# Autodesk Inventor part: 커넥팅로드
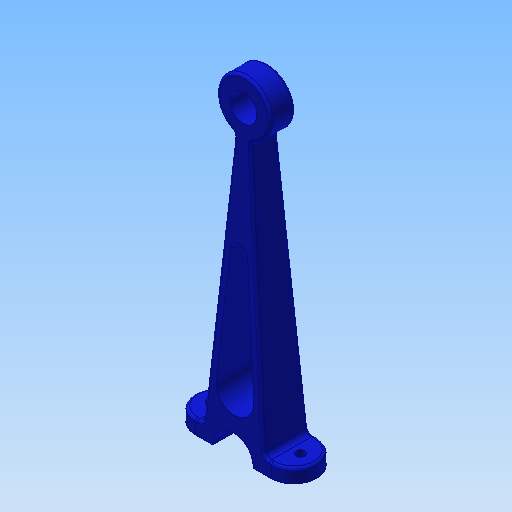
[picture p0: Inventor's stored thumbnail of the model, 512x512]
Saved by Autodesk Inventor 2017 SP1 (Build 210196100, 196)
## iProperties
Created: 2017-05
Part Number: 커넥팅로드
Material: 강철, 탄소
Document SubType Name: Modeling
Designer: mduedu
Density: 7.87 g/cm^3
Mass: 120.511 g
Surface Area: 85.3888 cm^2
Volume: 15.3127 cm^3
Appearance: 파란색 - 벽 페인트 - 무광
Author: mduedu
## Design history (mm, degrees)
sketch "스케치1"
  geometry: L1 (-22.5, 0)-(22.5, 0); L2 (22.5, 0)-(22.5, 5); L3 (-22.5, 5)-(-22.5, 0); L4 (-11.352, 5)-(-3, 100.461); L5 (0, 110)-(0, 0); L6 (11.352, 5)-(3, 100.461); L7 (22.5, 5)-(11.352, 5); L8 (-11.352, 5)-(-22.5, 5); C1 r 5 at (0, 110); A1 r 10 centre (0, 110) between (3, 100.461) and (-3, 100.461); 1 further point
  constraints: 16 end point, 4 parallel, 2 centre point, 2 coincident, 2 point on circle, 2 symmetric about line, 1 horizontal, 1 midpoint, 1 perpendicular, 1 vertical alignment
  dimensions: "d0" = 5 distance of L1.end L2.end; "d2" = 45 distance of L1.start L1.end; "d3" = 20 diameter of A1; "d4" = 10 diameter of C1; "d5" = 110 distance from line of L1 L5.start; "d6" = 5 deg angle of L5 L4; "d7" = 3 distance from line of L4.end L5
extrude "돌출1" new body sketch "스케치1" distance "d8" = 8.5; taper "d9" = 0 deg
sketch "스케치2"
  geometry: C1 r 7.5 at (0, 0); 1 further point
  constraints: 1 centre point, 1 coincident
  dimensions: "d10" = 15 diameter of C1
extrude "돌출2" cut sketch "스케치2" stored distance "d11" = 8.5; taper "d12" = 0 deg
sketch "스케치3"
  geometry: L1 (-3, 100.461)-(-11.352, 5) reference; L2 (11.352, 5)-(3, 100.461) reference; L3 (-3.154, 64.276)-(-6.975, 20.61); L4 (6.975, 20.61)-(3.154, 64.276); A1 r 3.166 centre (0, 64) between (3.154, 64.276) and (-3.154, 64.276); A2 r 7.001 centre (0, 20) between (-6.975, 20.61) and (6.975, 20.61); 1 further point
  constraints: 4 end point, 4 point on circle, 4 tangent, 2 centre point, 2 parallel, 1 vertical alignment
  dimensions: "d15" = 3 distance between parallel lines of L2 L4; "d16" = 44 distance of A2.centre A1.centre; "d17" = 20 distance of A2.centre point (0, 0)
extrude "돌출3" cut sketch "스케치3" stored distance "d18" = 8.5; taper "d19" = 0 deg
fillet "모깎기1" dims "d20" = 2
fillet "모깎기2" dims "d21" = 2
feature "면 기울기1" dims angle "d22" = 2 deg
fillet "모깎기3"
fillet "모깎기4"
fillet "모깎기5" dims "d28" = 1
sketch "스케치5"
  geometry: 3 further points
  constraints: 2 horizontal alignment
  dimensions: "d29" = 16.5 distance of point (-2.364, -7.36) point (14.136, -7.36); "d30" = 16.5 distance of point (30.636, -7.36) point (14.136, -7.36) (= d29)
sketch "스케치6"
  geometry: 2 further points
  constraints: 2 other
hole "구멍1" sketch "스케치6" at (-29.684, -7.36), (3.316, -7.36) diameter "d31" = 3.4; stored, may be unused: countersink angle "d35" = 90 deg, drill point angle "d37" = 0 deg; dims "d32" = 6, "d33" = 4, "d34" = 2, "d36" = 8
node "솔리드1"
mirror "대칭1"
other parameters: "d13" = 4, "d14" = 4
